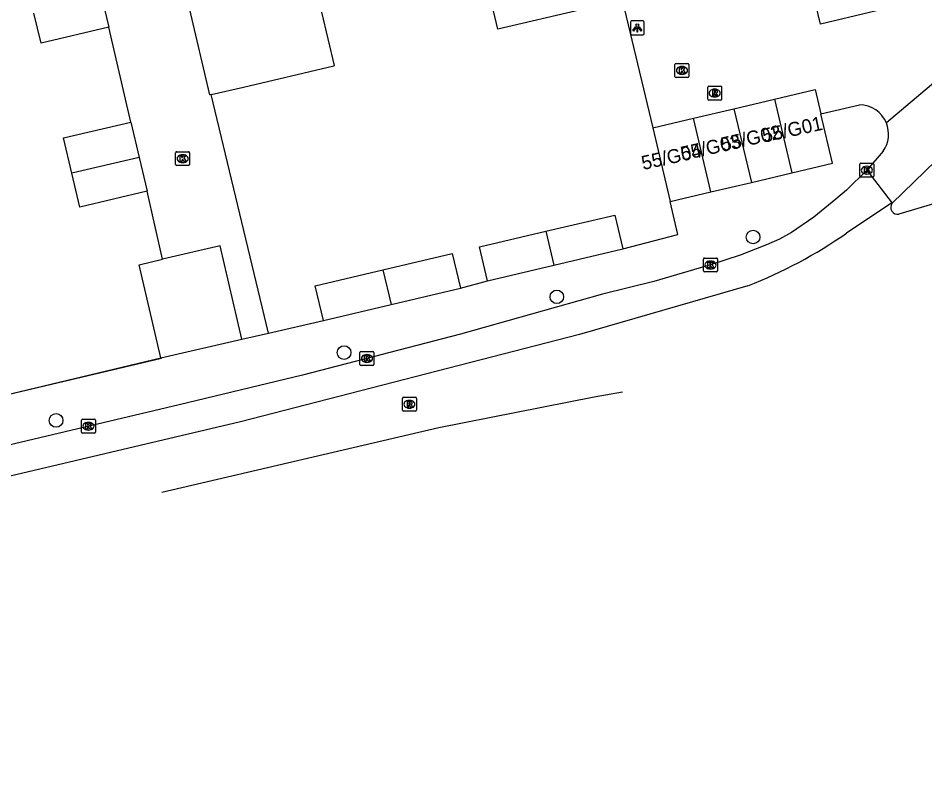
# Model space of a CAD drawing. Extents: x 158474 to 159560, y 388525 to 389605.
# Drawn here: x 159435.9 to 159501, y 388629 to 388683.1 of the extents above; entities that cross this region are included whole.
import ezdxf

# ---------------------------------------------------------------- set-up
doc = ezdxf.new("R2010")
doc.units = 0
for name, color, linetype in [('IMGEO_Boom', 7, 'Continuous'), ('IMGEO_Fietspad_gesloten', 7, 'Continuous'), ('IMGEO_Kolk', 7, 'Continuous'), ('IMGEO_Lichtpunt', 7, 'Continuous'), ('IMGEO_Muur', 7, 'Continuous'), ('IMGEO_Pand', 7, 'Continuous'), ('IMGEO_Pand_nummerreeks', 7, 'Continuous'), ('IMGEO_Rijbaan_lokaal_gesloten', 7, 'Continuous'), ('IMGEO_Rijbaan_lokaal_open', 7, 'Continuous'), ('IMGEO_Rioolput', 7, 'Continuous'), ('IMGEO_Voetpad_open', 7, 'Continuous')]:
    doc.layers.add(name, color=color, linetype=linetype)

msp = doc.modelspace()

# ---------------------------------------------------------------- linework, layer by layer
at = {"layer": 'IMGEO_Boom'}
for centre in [(159488.622, 388667.337), (159474.533, 388663.041), (159459.26, 388659.039), (159438.588, 388654.161)]:
    msp.add_circle(centre, 0.489, dxfattribs=at)
at = {"layer": 'IMGEO_Fietspad_gesloten'}
for points in [[(159498.599, 388669.761), (159503.318, 388674.355), (159504.725, 388675.7)], [(159497.962, 388673.51), (159496.788, 388672.144)]]:
    msp.add_lwpolyline(points, dxfattribs=at)
msp.add_arc((159496.247, 388674.725), 2.102, 324.67364, 22.57134, dxfattribs=at)
at = {"layer": 'IMGEO_Kolk'}
for p, q in [((159483.088, 388679.807), (159483.94, 388679.807)), ((159483.013, 388678.881), (159483.013, 388679.733)), ((159483.501, 388679.587), (159483.526, 388679.587)), ((159484.014, 388679.733), (159484.014, 388678.881)), ((159483.94, 388678.807), (159483.088, 388678.807)), ((159483.524, 388679.027), (159483.499, 388679.027)), ((159447.172, 388672.542), (159447.172, 388673.394)), ((159447.247, 388673.468), (159448.099, 388673.468)), ((159448.173, 388673.394), (159448.173, 388672.542)), ((159447.683, 388672.688), (159447.658, 388672.688)), ((159447.66, 388673.248), (159447.685, 388673.248)), ((159496.362, 388672.644), (159497.214, 388672.644)), ((159448.099, 388672.468), (159447.247, 388672.468)), ((159496.287, 388671.718), (159496.287, 388672.57)), ((159496.775, 388672.424), (159496.8, 388672.424)), ((159497.288, 388672.57), (159497.288, 388671.718)), ((159497.214, 388671.644), (159496.362, 388671.644)), ((159496.798, 388671.864), (159496.773, 388671.864)), ((159485.063, 388664.904), (159485.063, 388665.756)), ((159485.138, 388665.83), (159485.99, 388665.83)), ((159485.551, 388665.61), (159485.576, 388665.61)), ((159486.064, 388665.756), (159486.064, 388664.904)), ((159485.99, 388664.83), (159485.138, 388664.83)), ((159485.574, 388665.05), (159485.549, 388665.05)), ((159460.402, 388658.191), (159460.402, 388659.043)), ((159460.477, 388659.117), (159461.329, 388659.117)), ((159461.403, 388659.043), (159461.403, 388658.191)), ((159460.913, 388658.337), (159460.888, 388658.337)), ((159460.89, 388658.897), (159460.915, 388658.897)), ((159461.329, 388658.117), (159460.477, 388658.117)), ((159440.408, 388653.321), (159440.408, 388654.173)), ((159440.483, 388654.247), (159441.335, 388654.247)), ((159440.896, 388654.027), (159440.921, 388654.027)), ((159441.409, 388654.173), (159441.409, 388653.321)), ((159441.335, 388653.247), (159440.483, 388653.247)), ((159440.919, 388653.467), (159440.894, 388653.467))]:
    msp.add_line(p, q, dxfattribs=at)
for points in [[(159483.088, 388679.807), (159483.94, 388679.807)], [(159483.013, 388678.881), (159483.013, 388679.733)], [(159483.334, 388679.507), (159483.457, 388679.507), (159483.457, 388679.356), (159483.587, 388679.507), (159483.751, 388679.507), (159483.605, 388679.356), (159483.758, 388679.107), (159483.606, 388679.107), (159483.521, 388679.271), (159483.457, 388679.204), (159483.457, 388679.107), (159483.334, 388679.107), (159483.334, 388679.507)], [(159484.014, 388679.733), (159484.014, 388678.881)], [(159483.94, 388678.807), (159483.088, 388678.807)], [(159447.172, 388672.542), (159447.172, 388673.394)], [(159447.247, 388673.468), (159448.099, 388673.468)], [(159448.173, 388673.394), (159448.173, 388672.542)], [(159447.493, 388673.168), (159447.616, 388673.168), (159447.616, 388673.017), (159447.746, 388673.168), (159447.91, 388673.168), (159447.764, 388673.017), (159447.917, 388672.768), (159447.765, 388672.768), (159447.68, 388672.932), (159447.616, 388672.865), (159447.616, 388672.768), (159447.493, 388672.768), (159447.493, 388673.168)], [(159496.362, 388672.644), (159497.214, 388672.644)], [(159448.099, 388672.468), (159447.247, 388672.468)], [(159496.287, 388671.718), (159496.287, 388672.57)], [(159496.608, 388672.344), (159496.731, 388672.344), (159496.731, 388672.193), (159496.861, 388672.344), (159497.025, 388672.344), (159496.879, 388672.193), (159497.032, 388671.944), (159496.88, 388671.944), (159496.795, 388672.108), (159496.731, 388672.041), (159496.731, 388671.944), (159496.608, 388671.944), (159496.608, 388672.344)], [(159497.288, 388672.57), (159497.288, 388671.718)], [(159497.214, 388671.644), (159496.362, 388671.644)], [(159485.063, 388664.904), (159485.063, 388665.756)], [(159485.138, 388665.83), (159485.99, 388665.83)], [(159485.384, 388665.53), (159485.507, 388665.53), (159485.507, 388665.379), (159485.637, 388665.53), (159485.801, 388665.53), (159485.655, 388665.379), (159485.808, 388665.13), (159485.656, 388665.13), (159485.571, 388665.294), (159485.507, 388665.227), (159485.507, 388665.13), (159485.384, 388665.13), (159485.384, 388665.53)], [(159486.064, 388665.756), (159486.064, 388664.904)], [(159485.99, 388664.83), (159485.138, 388664.83)], [(159460.402, 388658.191), (159460.402, 388659.043)], [(159460.477, 388659.117), (159461.329, 388659.117)], [(159461.403, 388659.043), (159461.403, 388658.191)], [(159460.723, 388658.817), (159460.846, 388658.817), (159460.846, 388658.666), (159460.976, 388658.817), (159461.14, 388658.817), (159460.994, 388658.666), (159461.147, 388658.417), (159460.995, 388658.417), (159460.91, 388658.581), (159460.846, 388658.514), (159460.846, 388658.417), (159460.723, 388658.417), (159460.723, 388658.817)], [(159461.329, 388658.117), (159460.477, 388658.117)], [(159440.408, 388653.321), (159440.408, 388654.173)], [(159440.483, 388654.247), (159441.335, 388654.247)], [(159440.729, 388653.947), (159440.852, 388653.947), (159440.852, 388653.796), (159440.982, 388653.947), (159441.146, 388653.947), (159441, 388653.796), (159441.153, 388653.547), (159441.001, 388653.547), (159440.916, 388653.711), (159440.852, 388653.644), (159440.852, 388653.547), (159440.729, 388653.547), (159440.729, 388653.947)], [(159441.409, 388654.173), (159441.409, 388653.321)], [(159441.335, 388653.247), (159440.483, 388653.247)]]:
    msp.add_lwpolyline(points, dxfattribs=at)
for centre, start, end in [((159483.09, 388679.731), 91.55205, 178.44795), ((159483.09, 388679.731), 91.55205, 178.44795), ((159483.938, 388679.731), 1.55205, 88.44795), ((159483.938, 388679.731), 1.55205, 88.44795), ((159483.09, 388678.883), 181.55205, 268.44795), ((159483.09, 388678.883), 181.55205, 268.44795), ((159483.938, 388678.883), 271.55205, 358.44795), ((159483.938, 388678.883), 271.55205, 358.44795), ((159447.249, 388673.392), 91.55205, 178.44795), ((159447.249, 388673.392), 91.55205, 178.44795), ((159448.097, 388673.392), 1.55205, 88.44795), ((159448.097, 388673.392), 1.55205, 88.44795), ((159496.364, 388672.568), 91.55205, 178.44795), ((159496.364, 388672.568), 91.55205, 178.44795), ((159497.212, 388672.568), 1.55205, 88.44795), ((159497.212, 388672.568), 1.55205, 88.44795), ((159447.249, 388672.544), 181.55205, 268.44795), ((159447.249, 388672.544), 181.55205, 268.44795), ((159448.097, 388672.544), 271.55205, 358.44795), ((159448.097, 388672.544), 271.55205, 358.44795), ((159496.364, 388671.72), 181.55205, 268.44795), ((159496.364, 388671.72), 181.55205, 268.44795), ((159497.212, 388671.72), 271.55205, 358.44795), ((159497.212, 388671.72), 271.55205, 358.44795), ((159485.14, 388665.754), 91.55205, 178.44795), ((159485.14, 388665.754), 91.55205, 178.44795), ((159485.988, 388665.754), 1.55205, 88.44795), ((159485.988, 388665.754), 1.55205, 88.44795), ((159485.14, 388664.906), 181.55205, 268.44795), ((159485.14, 388664.906), 181.55205, 268.44795), ((159485.988, 388664.906), 271.55205, 358.44795), ((159485.988, 388664.906), 271.55205, 358.44795), ((159460.479, 388659.041), 91.55205, 178.44795), ((159460.479, 388659.041), 91.55205, 178.44795), ((159461.327, 388659.041), 1.55205, 88.44795), ((159461.327, 388659.041), 1.55205, 88.44795), ((159460.479, 388658.193), 181.55205, 268.44795), ((159460.479, 388658.193), 181.55205, 268.44795), ((159461.327, 388658.193), 271.55205, 358.44795), ((159461.327, 388658.193), 271.55205, 358.44795), ((159440.485, 388654.171), 91.55205, 178.44795), ((159440.485, 388654.171), 91.55205, 178.44795), ((159441.333, 388654.171), 1.55205, 88.44795), ((159441.333, 388654.171), 1.55205, 88.44795), ((159440.485, 388653.323), 181.55205, 268.44795), ((159440.485, 388653.323), 181.55205, 268.44795), ((159441.333, 388653.323), 271.55205, 358.44795), ((159441.333, 388653.323), 271.55205, 358.44795)]:
    msp.add_arc(centre, 0.0765, start, end, dxfattribs=at)
for centre, major_axis, ratio, start_param, end_param in [((159483.5, 388679.307), (-0.387, 0.002), 0.722429, 4.712389, 7.853982), ((159483.525, 388679.307), (-0.39, 0.002), 0.717154, 1.570796, 4.712389), ((159447.659, 388672.968), (-0.387, 0.002), 0.722429, 4.712389, 7.853982), ((159447.684, 388672.968), (-0.39, 0.002), 0.717154, 1.570796, 4.712389), ((159496.774, 388672.144), (-0.387, 0.002), 0.722429, 4.712389, 7.853982), ((159496.799, 388672.144), (-0.39, 0.002), 0.717154, 1.570796, 4.712389), ((159485.55, 388665.33), (-0.387, 0.002), 0.722429, 4.712389, 7.853982), ((159485.575, 388665.33), (-0.39, 0.002), 0.717154, 1.570796, 4.712389), ((159460.889, 388658.617), (-0.387, 0.002), 0.722429, 4.712389, 7.853982), ((159460.914, 388658.617), (-0.39, 0.002), 0.717154, 1.570796, 4.712389), ((159440.895, 388653.747), (-0.387, 0.002), 0.722429, 4.712389, 7.853982), ((159440.92, 388653.747), (-0.39, 0.002), 0.717154, 1.570796, 4.712389)]:
    msp.add_ellipse(centre, major_axis=major_axis, ratio=ratio, start_param=start_param, end_param=end_param, dxfattribs=at)
at = {"layer": 'IMGEO_Lichtpunt'}
for p, q in [((159479.812, 388682.763), (159479.812, 388681.956)), ((159479.812, 388682.763), (159479.812, 388681.956)), ((159480.714, 388682.858), (159479.906, 388682.858)), ((159480.714, 388682.858), (159479.906, 388682.858)), ((159480.808, 388681.956), (159480.808, 388682.763)), ((159480.808, 388681.956), (159480.808, 388682.763)), ((159479.906, 388681.862), (159480.714, 388681.862)), ((159479.906, 388681.862), (159480.714, 388681.862))]:
    msp.add_line(p, q, dxfattribs=at)
for points in [[(159480.186, 388682.427), (159480.225, 388682.399), (159480.037, 388682.137), (159479.999, 388682.164), (159480.186, 388682.427)], [(159480.288, 388682.379), (159480.335, 388682.379), (159480.335, 388682.057), (159480.288, 388682.057), (159480.288, 388682.379)], [(159480.398, 388682.399), (159480.436, 388682.426), (159480.623, 388682.164), (159480.584, 388682.136), (159480.398, 388682.399)]]:
    msp.add_lwpolyline(points, dxfattribs=at)
msp.add_circle((159480.311, 388682.561), 0.0994, dxfattribs=at)
for centre, start, end in [((159479.906, 388682.763), 90, 180), ((159479.906, 388682.763), 90, 180), ((159480.714, 388682.763), 0, 90), ((159480.714, 388682.763), 0, 90), ((159479.906, 388681.956), 180, 270), ((159479.906, 388681.956), 180, 270), ((159480.714, 388681.956), 270, 0), ((159480.714, 388681.956), 270, 360)]:
    msp.add_arc(centre, 0.0946, start, end, dxfattribs=at)
at = {"layer": 'IMGEO_Muur'}
msp.add_lwpolyline([(159434.283, 388655.838), (159446.152, 388658.635)], dxfattribs=at)
at = {"layer": 'IMGEO_Pand'}
for points in [[(159466.908, 388696.655), (159469.246, 388697.207), (159469.596, 388695.73), (159473.2, 388696.582), (159475.31, 388687.65), (159476.251, 388683.669), (159470.309, 388682.265), (159469.368, 388686.246)], [(159449.73, 388677.568), (159449.635, 388677.546), (159448.162, 388683.779), (159448.241, 388683.798), (159446.866, 388689.616)], [(159500.4, 388684.271), (159500, 388684.176), (159493.451, 388682.617), (159492.759, 388685.528), (159490.362, 388684.958), (159490.331, 388685.088)], [(159441.879, 388684.53), (159442.377, 388682.406)], [(159442.377, 388682.406), (159437.507, 388681.265), (159437.001, 388683.424)], [(159449.73, 388677.568), (159452.031, 388678.112), (159458.517, 388679.646), (159458.569, 388679.658), (159457.663, 388683.48)], [(159490.159, 388677.243), (159493.072, 388677.931), (159493.486, 388676.178)], [(159487.246, 388676.555), (159490.159, 388677.243)], [(159490.159, 388677.243), (159491.409, 388671.953)], [(159484.333, 388675.866), (159487.246, 388676.555)], [(159487.246, 388676.555), (159488.496, 388671.264)], [(159481.42, 388675.178), (159484.333, 388675.866)], [(159485.583, 388670.576), (159484.333, 388675.866)], [(159491.409, 388671.953), (159494.322, 388672.641), (159493.486, 388676.178)], [(159439.725, 388671.921), (159439.13, 388674.46), (159443.964, 388675.592)], [(159443.964, 388675.592), (159444.557, 388673.06)], [(159481.42, 388675.178), (159482.67, 388669.888)], [(159444.557, 388673.06), (159439.725, 388671.921)], [(159444.557, 388673.06), (159445.127, 388670.625)], [(159445.127, 388670.625), (159440.293, 388669.493), (159439.725, 388671.921)], [(159488.496, 388671.264), (159491.409, 388671.953)], [(159485.583, 388670.576), (159488.496, 388671.264)], [(159482.67, 388669.888), (159485.583, 388670.576)], [(159473.739, 388667.75), (159478.692, 388668.92), (159479.264, 388666.497)], [(159469.556, 388664.203), (159468.983, 388666.626), (159473.739, 388667.75)], [(159473.739, 388667.75), (159474.312, 388665.327)], [(159451.933, 388660.012), (159450.364, 388666.714), (159446.23, 388665.751)], [(159462.053, 388664.971), (159467.02, 388666.144), (159467.607, 388663.662)], [(159474.312, 388665.327), (159479.264, 388666.497)], [(159446.116, 388658.65), (159444.546, 388665.352), (159446.23, 388665.751)], [(159457.781, 388661.341), (159457.195, 388663.823), (159462.053, 388664.971)], [(159462.053, 388664.971), (159462.641, 388662.489)], [(159469.556, 388664.203), (159474.312, 388665.327)], [(159462.641, 388662.489), (159467.607, 388663.662)], [(159457.781, 388661.341), (159462.641, 388662.489)], [(159446.116, 388658.65), (159451.933, 388660.012)]]:
    msp.add_lwpolyline(points, dxfattribs=at)
at = {"layer": 'IMGEO_Rijbaan_lokaal_gesloten'}
for points in [[(159520.955, 388675.087), (159515.896, 388673.787), (159512.95, 388673.029), (159507.257, 388671.421), (159506.074, 388671.074), (159499.09, 388668.986)], [(159496.788, 388672.144), (159495.316, 388670.716), (159494.552, 388670.059), (159492.981, 388668.776), (159491.379, 388667.654), (159490.507, 388667.179), (159489.59, 388666.774), (159487.693, 388666.044), (159485.564, 388665.33), (159481.506, 388664.154), (159477.803, 388663.227), (159467.627, 388660.363), (159456.265, 388657.411), (159447.415, 388655.291), (159434.697, 388652.271), (159421.474, 388649.177), (159409.531, 388646.279), (159397.43, 388643.303), (159384.878, 388640.405), (159370.003, 388636.915), (159357.589, 388634.063), (159349.4, 388632.369), (159344.766, 388631.599), (159340.107, 388630.966)], [(159496.788, 388672.144), (159498.599, 388669.761)], [(159498.599, 388669.761), (159498.508, 388669.737), (159495.329, 388667.616)], [(159488.249, 388663.827), (159476.154, 388660.327), (159451.816, 388654.063), (159418.333, 388646.152), (159385.048, 388638.288), (159356.081, 388631.443), (159342.217, 388628.99)], [(159446.176, 388649.008), (159466.062, 388653.644), (159477.202, 388655.856), (159479.239, 388656.222)]]:
    msp.add_lwpolyline(points, dxfattribs=at)
for centre, radius, start, end in [((159498.992, 388669.467), 0.491, 143.18517, 281.52731), ((159475.279, 388696.571), 35.219, 291.60823, 304.70043)]:
    msp.add_arc(centre, radius, start, end, dxfattribs=at)
at = {"layer": 'IMGEO_Rijbaan_lokaal_open'}
for points in [[(159469.124, 388705.368), (159473.944, 388706.509), (159481.42, 388675.178)], [(159443.964, 388675.592), (159442.377, 388682.406)], [(159503.901, 388680.351), (159498.188, 388675.532)], [(159453.824, 388660.442), (159449.73, 388677.568)], [(159493.486, 388676.178), (159496.263, 388676.824)], [(159446.23, 388665.751), (159445.127, 388670.625)], [(159451.933, 388660.012), (159453.824, 388660.442)]]:
    msp.add_lwpolyline(points, dxfattribs=at)
msp.add_arc((159496.252, 388674.728), 2.097, 22.56458, 89.69886, dxfattribs=at)
at = {"layer": 'IMGEO_Rioolput'}
for p, q in [((159485.364, 388677.252), (159485.364, 388678.104)), ((159485.439, 388678.178), (159486.291, 388678.178)), ((159485.852, 388677.958), (159485.877, 388677.958)), ((159486.365, 388678.104), (159486.365, 388677.252)), ((159486.291, 388677.178), (159485.439, 388677.178)), ((159485.875, 388677.398), (159485.85, 388677.398)), ((159463.45, 388654.898), (159463.45, 388655.75)), ((159463.525, 388655.824), (159464.377, 388655.824)), ((159464.451, 388655.75), (159464.451, 388654.898)), ((159463.961, 388655.044), (159463.936, 388655.044)), ((159463.938, 388655.604), (159463.963, 388655.604)), ((159464.377, 388654.824), (159463.525, 388654.824))]:
    msp.add_line(p, q, dxfattribs=at)
for points in [[(159485.364, 388677.252), (159485.364, 388678.104)], [(159485.439, 388678.178), (159486.291, 388678.178)], [(159485.953, 388677.876), (159485.701, 388677.878), (159485.701, 388677.478)], [(159486.365, 388678.104), (159486.365, 388677.252)], [(159486.291, 388677.178), (159485.439, 388677.178)], [(159485.701, 388677.478), (159485.825, 388677.478), (159485.825, 388677.64), (159485.836, 388677.64)], [(159485.879, 388677.797), (159485.825, 388677.797), (159485.825, 388677.716)], [(159485.825, 388677.716), (159485.877, 388677.716)], [(159485.883, 388677.611), (159485.954, 388677.478), (159486.094, 388677.478), (159486.029, 388677.604)], [(159463.45, 388654.898), (159463.45, 388655.75)], [(159463.525, 388655.824), (159464.377, 388655.824)], [(159464.451, 388655.75), (159464.451, 388654.898)], [(159464.039, 388655.522), (159463.787, 388655.524), (159463.787, 388655.124)], [(159463.787, 388655.124), (159463.911, 388655.124), (159463.911, 388655.286), (159463.922, 388655.286)], [(159463.965, 388655.443), (159463.911, 388655.443), (159463.911, 388655.362)], [(159463.911, 388655.362), (159463.963, 388655.362)], [(159463.969, 388655.257), (159464.04, 388655.124), (159464.18, 388655.124), (159464.115, 388655.25)], [(159464.377, 388654.824), (159463.525, 388654.824)]]:
    msp.add_lwpolyline(points, dxfattribs=at)
for centre, radius, start, end in [((159485.441, 388678.102), 0.0765, 91.55205, 178.44795), ((159485.441, 388678.102), 0.0765, 91.55205, 178.44795), ((159485.952, 388677.766), 0.109, 350.36119, 89.41601), ((159486.289, 388678.102), 0.0765, 1.55205, 88.44795), ((159486.289, 388678.102), 0.0765, 1.55205, 88.44795), ((159485.441, 388677.254), 0.0765, 181.55205, 268.44795), ((159485.441, 388677.254), 0.0765, 181.55205, 268.44795), ((159485.835, 388677.587), 0.0533, 26.02933, 88.69889), ((159485.861, 388677.905), 0.19, 274.7715, 282.96867), ((159485.885, 388677.701), 0.0964, 77.00612, 93.18647), ((159485.899, 388677.758), 0.0378, 276.66336, 79.67722), ((159485.95, 388677.766), 0.112, 277.58423, 350.98172), ((159485.934, 388677.551), 0.108, 29.51342, 73.79051), ((159486.289, 388677.254), 0.0765, 271.55205, 358.44795), ((159486.289, 388677.254), 0.0765, 271.55205, 358.44795), ((159463.527, 388655.748), 0.0765, 91.55205, 178.44795), ((159463.527, 388655.748), 0.0765, 91.55205, 178.44795), ((159464.375, 388655.748), 0.0765, 1.55205, 88.44795), ((159464.375, 388655.748), 0.0765, 1.55205, 88.44795), ((159463.921, 388655.233), 0.0533, 26.02933, 88.69889), ((159463.947, 388655.551), 0.19, 274.7715, 282.96867), ((159463.971, 388655.347), 0.0964, 77.00612, 93.18647), ((159463.985, 388655.404), 0.0378, 276.66336, 79.67722), ((159464.038, 388655.412), 0.109, 350.36119, 89.41601), ((159464.036, 388655.412), 0.112, 277.58423, 350.98172), ((159464.02, 388655.197), 0.108, 29.51342, 73.79051), ((159463.527, 388654.9), 0.0765, 181.55205, 268.44795), ((159463.527, 388654.9), 0.0765, 181.55205, 268.44795), ((159464.375, 388654.9), 0.0765, 271.55205, 358.44795), ((159464.375, 388654.9), 0.0765, 271.55205, 358.44795)]:
    msp.add_arc(centre, radius, start, end, dxfattribs=at)
for centre, major_axis, ratio, start_param, end_param in [((159485.851, 388677.678), (-0.387, 0.002), 0.722429, 4.712389, 7.853982), ((159485.876, 388677.678), (-0.39, 0.002), 0.717154, 1.570796, 4.712389), ((159463.937, 388655.324), (-0.387, 0.002), 0.722429, 4.712389, 7.853982), ((159463.962, 388655.324), (-0.39, 0.002), 0.717154, 1.570796, 4.712389)]:
    msp.add_ellipse(centre, major_axis=major_axis, ratio=ratio, start_param=start_param, end_param=end_param, dxfattribs=at)
at = {"layer": 'IMGEO_Voetpad_open'}
for points in [[(159479.264, 388666.497), (159483.225, 388667.513), (159482.67, 388669.888)], [(159467.607, 388663.662), (159469.556, 388664.203)], [(159453.824, 388660.442), (159457.781, 388661.341)], [(159434.283, 388655.838), (159446.116, 388658.65)]]:
    msp.add_lwpolyline(points, dxfattribs=at)

# ---------------------------------------------------------------- texts
at = {"layer": 'IMGEO_Pand_nummerreeks'}
for s, rotation, p in [('55/G01', 12.45037, (159489.397, 388674.109)), ('55/G02', 12.44762, (159486.434, 388673.484)), ('55/G03', 12.44762, (159483.535, 388672.816)), ('55/G04', 12.44762, (159480.727, 388672.15))]:
    msp.add_text(s, height=1, rotation=rotation, dxfattribs=at).set_placement(p)

doc.saveas('drawing.dxf')
